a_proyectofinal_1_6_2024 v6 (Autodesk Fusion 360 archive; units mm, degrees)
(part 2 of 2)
sketch "Sketch3" plane through (0, 0, 0) normal (0, 1, 0) x axis (1, 0, 0)
  line L1 (95, -25) -> (69.8084, -49.7859)
  line L2 (96.1204, -94.6636) -> (71.4078, -69.5464)
  line L3 (44.8151, -70.2307) -> (23.816, -95.5593)
  line L4 (50.792, -46.161) -> (24, -25)
  line L5 (27.1087, -97.4894) -> (46.6834, -72.3674)
  line L6 (98.0341, -92.1823) -> (72.9099, -66.6469)
  line L7 (97.8108, -27.8066) -> (71.4947, -51.9813)
  line L8 (22, -27) -> (47.5374, -48.2633)
  line L9 (27.1087, -97.4894) -> (23.816, -95.5593)
  line L10 (98.0341, -92.1823) -> (96.1204, -94.6636)
  line L11 (95, -25) -> (97.8108, -27.8066)
  line L12 (22, -27) -> (24, -25)
  circle C1 centre (57.8749, -60.6967) radius 16.1696
  point P3 (69.8084, -49.7859)
  point P8 (44.8151, -70.2307)
  point P10 (50.792, -46.161)
  point P5 (71.4078, -69.5464)
  point P11 (46.6834, -72.3674)
  point P13 (72.9099, -66.6469)
  point P15 (71.4947, -51.9813)
  point P17 (47.5374, -48.2633)
  perpendicular L1 L2
  coincident C1 P3
  coincident C1 P8
  coincident C1 P10
  coincident C1 P5
  coincident C1 P11
  coincident C1 P13
  parallel L2 L6
  coincident C1 P15
  coincident C1 P17
extrude "Extrude3" add sketch "Sketch3" along normal blind 10
fillet "Fillet1" radius 3
fillet "Fillet2" radius 3
fillet "Fillet3" radius 3
fillet "Fillet4" radius 3
sketch "Sketch4" plane through (0, 15, 0) normal (0, 1, 0) x axis (-1, 0, 0)
  line L1 (0, 117) -> (0, 3)
  line L2 (-117, 120) -> (-3, 120)
  line L3 (-120, 3) -> (-120, 117)
  line L4 (-3, 0) -> (-117, 0)
  curve K1 (-55.9929, 76.7737) -> (-65, 75)
  curve K2 (-42.3656, 55.7132) -> (-42.3656, 64.7391)
  curve K3 (-61.8332, 45) -> (-55, 45)
  curve K4 (-74.2217, 62.2614) -> (-72.6081, 55.7132)
  curve K5 (-72.6081, 55.7132) -> (-74.2217, 62.2614)
  curve K6 (-55, 45) -> (-61.8332, 45)
  curve K7 (-42.3656, 55.7132) -> (-42.3656, 64.7391)
  curve K8 (-55.9929, 76.7737) -> (-65, 75)
  arc A1 centre (-3, 3) radius 3 clockwise from (0, 3) to (-3, 0)
  arc A2 centre (-3, 117) radius 3 clockwise from (-3, 120) to (0, 117)
  arc A3 centre (-117, 117) radius 3 clockwise from (-120, 117) to (-117, 120)
  arc A4 centre (-117, 3) radius 3 clockwise from (-117, 0) to (-120, 3)
  circle C1 centre (-60, 60) radius 50
  point P16 (-77.8984, 106.6867)
  point P20 (-11.884, 73.5958)
  point P24 (-55, 10.2506)
  point P28 (-108.4695, 47.7238)
  coincident C1 P16
  coincident C1 P20
  coincident C1 P24
  coincident C1 P28
extrude "Extrude4" new body sketch "Sketch4" profile of C1 K1 K2 K3 K4 K5 K6 K7 K8 along normal blind 5
move "Move1"
move "Move2"
move "Move3"
move "Move4"

design "a_centro_adelante_final"
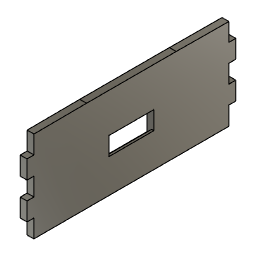
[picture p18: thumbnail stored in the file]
sketch "Sketch1" plane through (0, 0, 0) normal (1, 0, 0) x axis (0, 1, 0)
  line L1 (15, 0) -> (444.8, 0)
  line L2 (15.2, 160.15) -> (15.2, 200)
  line L3 (0, 160.15) -> (15.2, 160.15)
  line L4 (0, 119.6381) -> (15.2, 119.6381)
  line L5 (15.2, 79.7881) -> (0, 79.7881)
  line L6 (15.2, 119.6381) -> (15.2, 79.7881)
  line L7 (444.8, 160.15) -> (460, 160.15)
  line L8 (460, 120.3) -> (444.8, 120.3)
  line L9 (460, 160.15) -> (460, 120.3)
  line L10 (444.8, 160.15) -> (444.8, 200)
  line L11 (460, 160.15) -> (444.8, 160.15)
  line L12 (444.8, 120.3) -> (460, 120.3)
  line L13 (444.8, 80.45) -> (444.8, 120.3)
  line L14 (460, 80.45) -> (444.8, 80.45)
  line L15 (444.8, 200) -> (328.7889, 200.8074)
  line L16 (460, 120.3) -> (460, 160.15)
  line L17 (460, 40.6) -> (460, 80.45)
  line L18 (15.2, 160.15) -> (15.2, 200)
  line L19 (0, 160.15) -> (15.2, 160.15)
  line L20 (0, 79.7881) -> (0, 39.894)
  line L21 (0, 160.15) -> (0, 119.6381)
  line L22 (15, 39.894) -> (0, 39.894)
  line L23 (15, 0) -> (15, 39.894)
  line L24 (0, 0) -> (15, 0)
  line L25 (444.8, 80.45) -> (460, 80.45)
  line L26 (460, 40.6) -> (444.8, 40.6)
  line L27 (460, 80.45) -> (460, 40.6)
  line L28 (460, 40.6) -> (444.8, 40.6)
  line L29 (444.8, 40.6) -> (444.8, 0)
  line L30 (131.2111, 200.8074) -> (15.2, 200)
  line L31 (279.5, 64.4277) -> (180.5, 124.4277)
  line L32 (180.5, 64.4277) -> (279.5, 124.4277)
  line L33 (279.5, 114.5277) -> (180.5, 114.5277)
  line L34 (279.5, 74.3277) -> (279.5, 114.5277)
  line L35 (180.5, 74.3277) -> (279.5, 74.3277)
  line L36 (180.5, 114.5277) -> (180.5, 74.3277)
  line L37 (279.5, 74.3277) -> (180.5, 114.5277)
  line L38 (180.5, 74.3277) -> (279.5, 114.5277)
  line L39 (131.2111, 200.8074) -> (328.7889, 200.8074)
  point P35 (230, 94.4277)
  point P40 (230, 94.4277)
  point P7 (15.2, 119.6381)
  point P10 (15.2, 79.7881)
  point P11 (460, 160.15)
  point P12 (444.8, 160.15)
  point P14 (460, 120.3)
  point P19 (460, 80.45)
  point P26 (444.8, 80.45)
  point P28 (460, 40.6)
  point P37 (279.5, 114.5277)
  point P38 (279.5, 74.3277)
  horizontal L1
  vertical L20
  vertical L2
  horizontal L3
  horizontal L4
  horizontal L5
  vertical L6
  horizontal L7
  horizontal L8
  vertical L9
  vertical L10
  horizontal L11
  horizontal L12
  vertical L13
  horizontal L14
  collinear L16 L17
  vertical L18
  horizontal L19
  collinear L20 L21
  horizontal L22
  vertical L23
  horizontal L24
  horizontal L25
  horizontal L26
  vertical L27
  horizontal L28
  vertical L29
  coincident L31 P35
  coincident L32 P35
  horizontal L33
  perpendicular L33 L34
  parallel L33 L35
  parallel L34 L36
  coincident L37 P40
  coincident L38 P40
  coincident P35 P40
  horizontal L39
  dimension "d10" distance P7 P10 = 39.85
  dimension "d11" distance P11 P12 = 15.2
  dimension "d14" distance P14 P19 = 39.85
  dimension "d15" distance P19 P26 = 15.2
  dimension "d16" distance P19 P28 = 39.85
  dimension "d22" distance P37 P38 = 40.2
extrude "Extrude1" new body sketch "Sketch1" profile of L17 L1 L21 L2 L3 L4 L5 L6 L7 L8 L9 L10 L11 L12 L13 L14 L15 L18 L19 L22 L23 L25 L26 L27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 along normal blind 15
extrude "Extrude2" cut sketch "Sketch1" profile of L33 L34 L35 L36 along normal blind 20
sketch "Sketch2" plane through (0, 0, 0) normal (1, 0, 0) x axis (0, 1, 0)
  line L1 (180.5, 125) -> (279.5, 125)
  line L2 (279.5, 65) -> (180.5, 65)
  line L3 (279.5, 125) -> (279.5, 65)
  line L4 (180.5, 65) -> (279.5, 125)
  line L5 (279.5, 65) -> (180.5, 125)
  line L6 (180.5, 65) -> (180.5, 125)
  point P6 (230, 95)
  point P4 (180.5, 65)
  point P5 (279.5, 65)
  point P3 (180.5, 125)
  horizontal L1
  parallel L1 L2
  coincident L4 P6
  coincident L5 P6
  perpendicular L1 L6
  dimension "d25" distance P4 P5 = 99
  dimension "d26" distance P3 P4 = 60
extrude "Extrude3" cut sketch "Sketch2" profile of L1 L2 L3 L6 along normal blind 10

design "lateralIzq_projectfinal"
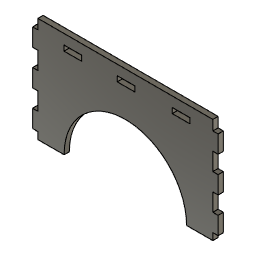
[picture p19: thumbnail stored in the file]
sketch "Sketch1" plane through (0, 0, 0) normal (0, 1, 0) x axis (1, 0, 0)
  line L1 (-500, 0) -> (0, 0)
  line L2 (-273.115, 28.51) -> (-222.765, 28.51)
  line L3 (-273.115, 43.71) -> (-273.115, 28.51)
  line L4 (-222.765, 43.71) -> (-273.115, 43.71)
  line L5 (-222.765, 28.51) -> (-222.765, 43.71)
  line L6 (-116.0096, 28.51) -> (-65.6596, 28.51)
  line L7 (-116.0096, 43.71) -> (-116.0096, 28.51)
  line L8 (-65.6596, 43.71) -> (-116.0096, 43.71)
  line L9 (-65.6596, 28.51) -> (-65.6596, 43.71)
  line L10 (-273.115, 43.71) -> (-273.115, 28.51)
  line L11 (-273.115, 28.51) -> (-222.765, 28.51)
  line L12 (-222.765, 43.71) -> (-273.115, 43.71)
  line L13 (-222.765, 28.51) -> (-222.765, 43.71)
  line L14 (-425.3783, 28.51) -> (-375.0283, 28.51)
  line L15 (-425.3783, 43.71) -> (-425.3783, 28.51)
  line L16 (-375.0283, 43.71) -> (-425.3783, 43.71)
  line L17 (-375.0283, 28.51) -> (-375.0283, 43.71)
  line L18 (-425, 300) -> (-500, 300)
  line L19 (0, 300) -> (-75, 300)
  line L20 (0, 28.51) -> (0, 0)
  line L21 (15.2, 28.51) -> (0, 28.51)
  line L22 (15.2, 78.86) -> (15.2, 28.51)
  line L23 (0, 78.86) -> (15.2, 78.86)
  line L24 (0, 129.21) -> (0, 78.86)
  line L25 (15.2, 129.21) -> (0, 129.21)
  line L26 (0, 129.21) -> (15.2, 129.21)
  line L27 (15.2, 129.21) -> (15.2, 179.56)
  line L28 (0, 179.56) -> (15.2, 179.56)
  line L29 (0, 229.91) -> (0, 179.56)
  line L30 (15.2, 229.91) -> (0, 229.91)
  line L31 (15.2, 280.26) -> (0, 280.26)
  line L32 (15.2, 229.91) -> (15.2, 280.26)
  line L33 (-515, 179.56) -> (-499.8, 179.56)
  line L34 (-499.8, 129.21) -> (-515, 129.21)
  line L35 (-515, 129.21) -> (-499.8, 129.21)
  line L36 (-515, 78.86) -> (-499.8, 78.86)
  line L37 (-499.8, 28.51) -> (-515, 28.51)
  line L38 (-499.8, 280.26) -> (-515, 280.26)
  line L39 (-499.8, 229.91) -> (-515, 229.91)
  line L40 (-515, 28.51) -> (-515, 78.86)
  line L41 (-515, 280.26) -> (-515, 229.91)
  line L42 (-515, 179.56) -> (-515, 129.21)
  line L43 (-500, 28.51) -> (-500, 0)
  line L44 (-500, 129.21) -> (-500, 78.86)
  line L45 (-500, 229.91) -> (-500, 179.56)
  line L46 (-500, 300) -> (-500, 280.26)
  line L47 (0, 300) -> (0, 280.26)
  arc A1 centre (-250, 300) radius 175 clockwise from (-75, 300) to (-425, 300)
  point P1 (0, 0)
  point P2 (0, 0)
  point P23 (-75, 300)
  point P6 (-250, 300)
  point P25 (0, 0)
  point P55 (-500, 28.51)
  point P56 (-500, 78.86)
  point P57 (-500, 129.21)
  point P58 (-500, 179.56)
  point P59 (-500, 229.91)
  point P60 (-500, 280.26)
  point P3 (-500, 0)
  point P5 (0, 300)
  point P8 (-222.765, 28.51)
  point P9 (-273.115, 28.51)
  point P11 (-222.765, 43.71)
  point P7 (-65.6596, 28.51)
  point P12 (-116.0096, 28.51)
  point P14 (-65.6596, 43.71)
  point P15 (-273.115, 28.51)
  point P16 (-222.765, 28.51)
  point P17 (-222.765, 43.71)
  point P19 (-375.0283, 28.51)
  point P20 (-425.3783, 28.51)
  point P22 (-375.0283, 43.71)
  point P26 (0, 28.51)
  point P27 (15.2, 28.51)
  point P39 (-515, 28.51)
  point P48 (-499.8, 28.51)
  point P43 (-515, 78.86)
  point P47 (-499.8, 78.86)
  point P40 (-499.8, 179.56)
  point P45 (-499.8, 129.21)
  point P53 (-515, 179.56)
  point P49 (-515, 229.91)
  point P52 (-499.8, 229.91)
  point P51 (-499.8, 280.26)
  horizontal L1
  vertical L43
  horizontal L18
  coincident P1 P2
  horizontal L2
  vertical L3
  horizontal L4
  vertical L5
  horizontal L6
  vertical L7
  horizontal L8
  vertical L9
  horizontal L11
  vertical L10
  horizontal L12
  vertical L13
  horizontal L14
  vertical L15
  horizontal L16
  vertical L17
  coincident P23 L18
  collinear L18 L19
  coincident P6 L18
  coincident P1 P25
  perpendicular L1 L20
  horizontal L21
  vertical L22
  horizontal L23
  horizontal L25
  vertical L27
  horizontal L28
  horizontal L30
  horizontal L31
  vertical L32
  horizontal L37
  vertical L40
  horizontal L36
  horizontal L34
  vertical L42
  horizontal L33
  horizontal L39
  vertical L41
  horizontal L38
  coincident L37 P55
  coincident L36 P56
  collinear L43 L44
  coincident L34 P57
  coincident L33 P58
  collinear L44 L45
  coincident L39 P59
  coincident L38 P60
  collinear L45 L46
  perpendicular L31 L47
  dimension "d1" distance P2 P3 = 500
  dimension "d2" distance P2 P5 = 300
  dimension "d6" distance P8 P9 = 50.35
  dimension "d7" distance P8 P11 = 15.2
  dimension "d8" distance P7 P12 = 50.35
  dimension "d9" distance P7 P14 = 15.2
  dimension "d10" distance P15 P16 = 50.35
  dimension "d11" distance P16 P17 = 15.2
  dimension "d13" distance P19 P20 = 50.35
  dimension "d14" distance P19 P22 = 15.2
  dimension "d17" distance P25 P26 = 28.51
  dimension "d18" distance P26 P27 = 15.2
  dimension "d28" distance P39 P48 = 15.2
  dimension "d30" distance P43 P47 = 15.2
  dimension "d32" distance P40 P45 = 50.35
  dimension "d33" distance P40 P53 = 15.2
  dimension "d34" distance P49 P52 = 15.2
  dimension "d35" distance P51 P52 = 50.35
extrude "Extrude1" new body sketch "Sketch1" profile of L1 L46 L19 A1 L2 L3 L4 L5 L6 L7 L8 L9 L10 L11 L12 L13 L14 L15 L16 L17 along normal blind 15

design "vidrio"
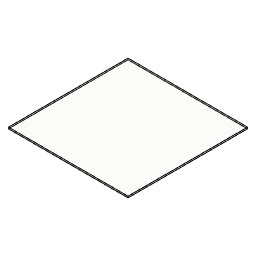
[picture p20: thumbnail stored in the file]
sketch "Sketch1" plane through (0, 0, 0) normal (0, 0, 1) x axis (1, 0, 0)
  line L1 (427, 0) -> (0, 0)
  line L2 (427, 427) -> (427, 0)
  line L3 (0, 427) -> (427, 427)
  line L4 (0, 0) -> (0, 427)
  point P1 (0, 0)
  point P2 (0, 0)
  point P3 (427, 0)
  point P5 (0, 427)
  horizontal L1
  vertical L2
  horizontal L3
  vertical L4
  coincident P1 P2
  dimension "d1" distance P2 P3 = 427
  dimension "d2" distance P2 P5 = 427
extrude "Extrude1" new body sketch "Sketch1" along normal blind 5

design "soporte_vidrio"
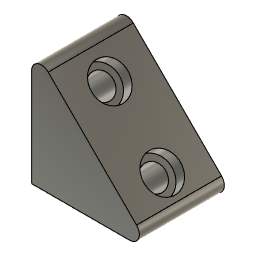
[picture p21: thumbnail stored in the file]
sketch "Sketch1" plane through (0, 0, 0) normal (0, 1, 0) x axis (1, 0, 0)
  line L1 (50, 0) -> (0, 0)
  line L2 (0, 0) -> (0, -50)
  line L3 (50, 0) -> (0, -50)
  point P1 (0, 0)
  point P2 (0, 0)
  horizontal L1
  vertical L2
  coincident P1 P2
extrude "Extrude1" new body sketch "Sketch1" along normal blind 35
fillet "Fillet1" radius 4
fillet "Fillet2" radius 4
sketch "Sketch2" plane through (25, 0, 25) normal (0.7071, 0, 0.7071) x axis (0, 1, 0)
  line L1 (35, -25.6985) -> (0, -25.6985)
  line L2 (35, 25.6985) -> (35, -25.6985)
  line L3 (0, 25.6985) -> (35, 25.6985)
  line L4 (0, -25.6985) -> (0, 25.6985)
  circle C1 centre (17.3639, 14.4089) radius 5
  circle C2 centre (17.2701, -16.2573) radius 5
  dimension "d7" diameter C1 = 10
  dimension "d8" diameter C2 = 10
extrude "Extrude2" cut sketch "Sketch2" profile of C1 C2 against normal blind 35
sketch "Sketch3" plane through (25, 0, 25) normal (0.7071, 0, 0.7071) x axis (0, 1, 0)
  line L1 (35, -25.6985) -> (0, -25.6985)
  line L2 (35, 25.6985) -> (35, -25.6985)
  line L3 (0, 25.6985) -> (35, 25.6985)
  line L4 (0, -25.6985) -> (0, 25.6985)
  circle C1 centre (17.3639, 14.4089) radius 5
  circle C2 centre (17.2701, -16.2573) radius 5
  circle C3 centre (17.3639, 14.4089) radius 7.5
  circle C4 centre (17.2701, -16.2573) radius 7.5
  concentric C1 C3
  concentric C2 C4
  dimension "d11" diameter C3 = 15
  dimension "d12" diameter C4 = 15
extrude "Extrude3" cut sketch "Sketch3" profile of C1 C2 C3 C4 along normal blind 5 and against normal blind 5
